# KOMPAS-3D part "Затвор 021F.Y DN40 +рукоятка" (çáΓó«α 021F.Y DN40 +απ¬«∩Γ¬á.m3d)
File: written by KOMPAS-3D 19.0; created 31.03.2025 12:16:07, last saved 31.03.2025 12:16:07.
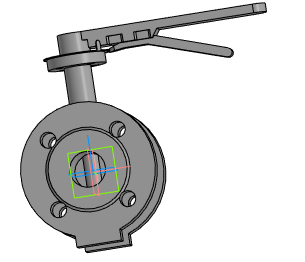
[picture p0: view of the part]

Document properties: Автор: Евгений; Полное имя файла: Затвор 021F.Y DN40 +рукоятка.a3d

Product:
- Part/product: Затвор 021F.Y DN40 +рукоятка
    Масса: 8.01941

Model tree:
1. Операция без истории:1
